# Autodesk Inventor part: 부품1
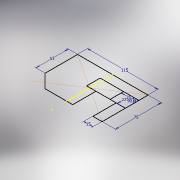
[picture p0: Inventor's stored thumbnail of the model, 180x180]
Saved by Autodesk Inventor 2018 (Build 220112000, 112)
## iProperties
Created: 2019-06
Part Number: 부품1
Material: 일반
Document SubType Name: Modeling
Designer: 6507_12
Density: 1 g/cm^3
Appearance: 기본값
Author: 6507_12
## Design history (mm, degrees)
sketch "스케치1"
  geometry: 1 further point
sketch "스케치2"
  geometry: L1 (57.5, 98.884)-(-57.5, 98.884); L2 (-57.5, 98.884)-(-57.5, 45.884); L3 (57.5, 23.884)-(57.5, 98.884); L4 (57.5, 98.884)-(-57.5, 23.884); L5 (-57.5, 98.884)-(57.5, 23.884); L6 (-57.5, 98.884)-(-57.5, 45.884); L7 (-57.5, 45.884)-(-35.5, 23.884); L8 (57.5, 23.884)-(42.5, 23.884); L9 (42.5, 23.884)-(42.5, 61.884); L10 (42.5, 61.884)-(57.5, 61.884); L11 (-35.5, 23.884)-(9.5, 23.884); L12 (9.5, 23.884)-(9.5, 61.884); L13 (9.5, 61.884)-(42.5, 61.884); L14 (-35.5, 23.884)-(9.5, 23.884); L15 (42.5, 23.884)-(57.5, 23.884); L16 (57.5, 61.884)-(57.5, 83.884); L17 (57.5, 83.884)-(32.5, 83.884); L18 (32.5, 83.884)-(32.5, 61.884); L19 (32.5, 83.884)-(-5.68, 83.884); L20 (-5.68, 83.884)-(-5.68, 61.884); L21 (-5.68, 61.884)-(32.5, 61.884); 2 further points
  constraints: 42 end point, 5 perpendicular, 3 parallel, 3 point on line, 2 horizontal, 2 midpoint, 1 collinear, 1 vertical
  dimensions: "d0" = 115 distance of L1.start L1.end; "d1" = 75 distance of L3.start L1.start; "d3" = 53 distance of L2.end L1.end; "d5" = 15 distance of L3.start L8.end; "d11" = 22 distance of L10.end L16.end; "d14" = 25 distance of L16.end L17.end; "d15" = 90 deg angle of L17 L16
sketch "스케치3"
  geometry: L1 (98.884, 0)-(45.884, 0) reference; L2 (45.884, 0)-(23.884, 0) reference; L3 (23.884, 0)-(61.884, 0) reference; L4 (23.884, 0)-(61.884, 0) reference; 4 further points
sketch "스케치4"
  geometry: 1 further point
